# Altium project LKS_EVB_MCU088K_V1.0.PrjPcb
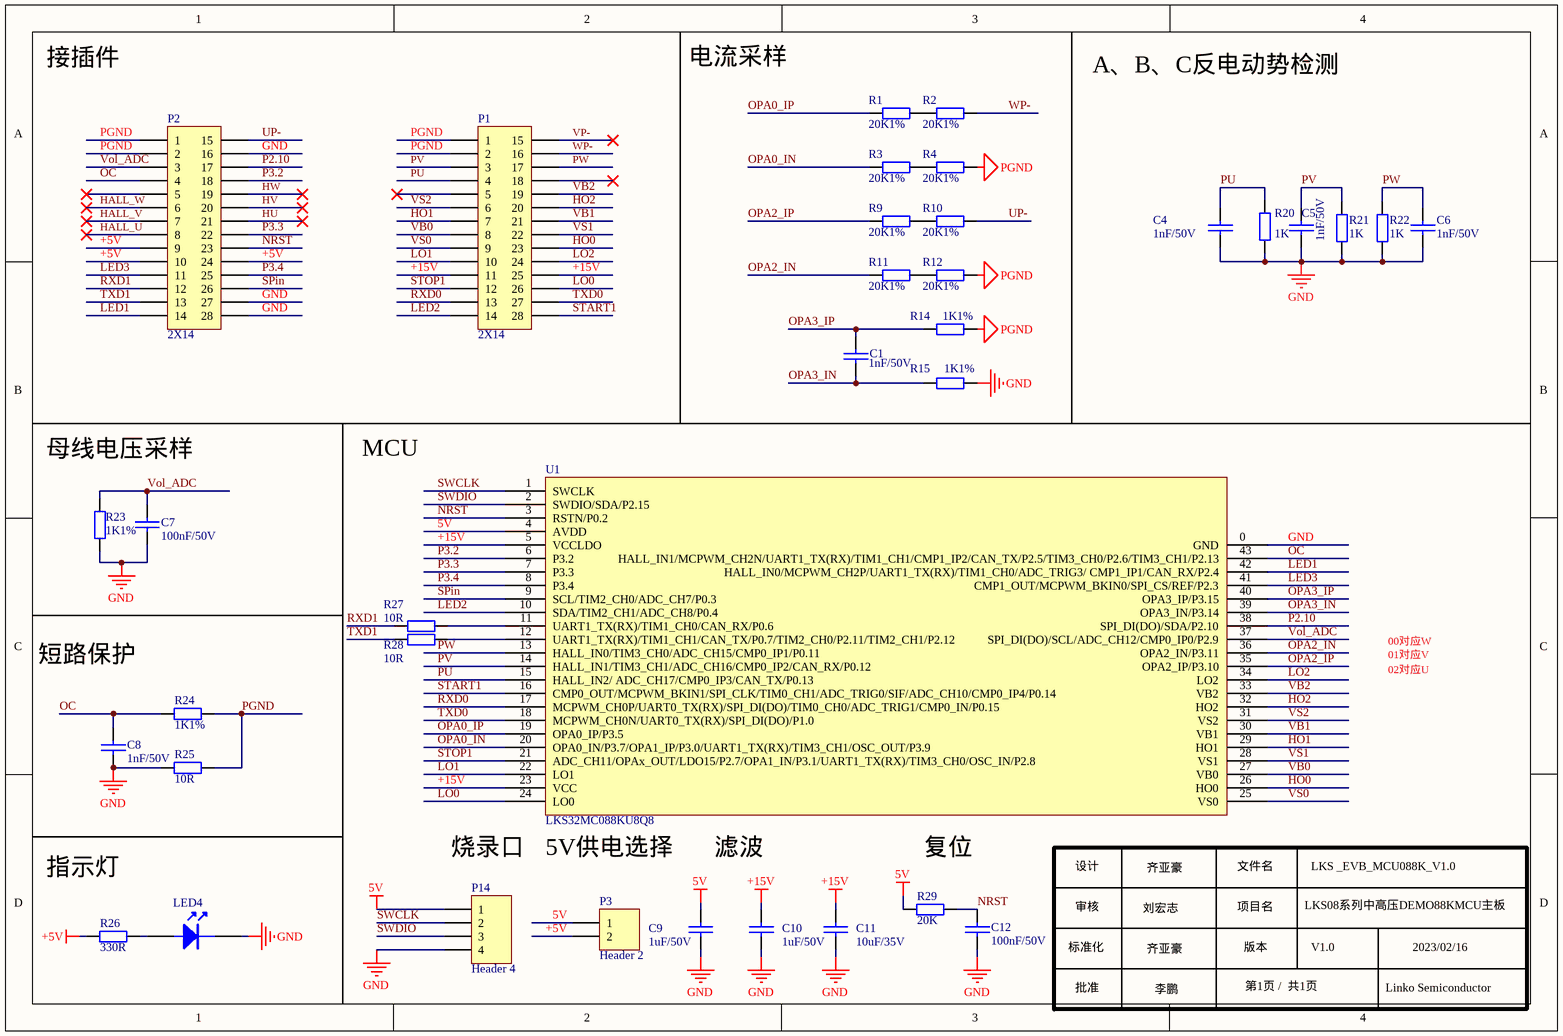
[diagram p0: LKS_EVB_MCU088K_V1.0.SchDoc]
1 sheet, 36 parts. Net scope: global (net labels, ports and power ports of the same name join across sheets).
Board file: LKS_EVB_MCU088K_V1.0.PcbDoc

## Sheet LKS_EVB_MCU088K_V1.0.SchDoc
size A4; SheetNumber: 1; SheetTotal: 1

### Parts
C1  1nF/50V  [0603C]
C4  1nF/50V  [0603C]
C5  1nF/50V  [0603C]
C6  1nF/50V  [0603C]
C7  100nF/50V  [0603C]
C8  1nF/50V  [0603C]
C9  1uF/50V  [0603C]
C10  1uF/50V  [0603C]
C11  10uF/35V  [0805C]
C12  100nF/50V  [0603C]
LED4  LED  [LED 0603R]  (value not drawn)
P1  2X14  [HDR 2X14 底层]
P2  2X14  [HDR 2X14 底层]
P3  Header 2  [HDR 1X2]
P14  Header 4  [HDR 1X4]
R1  20K1%  [0603R]
R2  20K1%  [0603R]
R3  20K1%  [0603R]
R4  20K1%  [0603R]
R9  20K1%  [0603R]
R10  20K1%  [0603R]
R11  20K1%  [0603R]
R12  20K1%  [0603R]
R14  1K1%  [0603R]
R15  1K1%  [0603R]
R20  1K  [0603R]
R21  1K  [0603R]
R22  1K  [0603R]
R23  1K1%  [0603R]
R24  1K1%  [0603R]
R25  10R  [0603R]
R26  330R  [0603R]
R27  10R  [0603R]
R28  10R  [0603R]
R29  20K  [0603R]
U1  LKS32MC088KU8Q8  [QFN43]

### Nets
5V: C9.2 P3.1 P14.1 R29.1 U1.4(AVDD)
+5V: P2.9 P2.10 P2.24 P3.2 R26.1
+15V: C10.2 C11.2 P1.11 P1.25 U1.5(VCCLDO) U1.23(VCC)
GND: C4.2 C5.2 C6.2 C7.1 C8.1 C9.1 C10.1 C11.1 C12.2 LED4.2(K) P2.16 P2.27 P2.28 P14.4 R15.1 R20.2 R21.2 R22.2 R23.1 R25.2 U1.0(GND)
PGND: P1.1 P1.2 P2.1 P2.2 R4.1 R12.1 R14.1 R24.2 R25.1
HALL_U: P2.8
HALL_V: P2.7
HALL_W: P2.6
HO0: P1.23 U1.26(HO0)
HO1: P1.7 U1.29(HO1)
HO2: P1.20 U1.32(HO2)
HU: P2.21
HV: P2.20
HW: P2.19
LED1: P2.14 U1.42(HALL_IN0/MCPWM_CH2P/UART1_TX(RX)/TIM1_CH0/ADC_TRIG3/_CMP1_IP1/CAN_RX/P2.4)
LED2: P1.14 U1.10(SDA/TIM2_CH1/ADC_CH8/P0.4)
LED3: P2.11 U1.41(CMP1_OUT/MCPWM_BKIN0/SPI_CS/REF/P2.3)
LO0: P1.26 U1.24(LO0)
LO1: P1.10 U1.22(LO1)
LO2: P1.24 U1.34(LO2)
NRST: C12.1 P2.23 R29.2 U1.3(RSTN/P0.2)
OC: C8.2 P2.4 R24.1 U1.43(HALL_IN1/MCPWM_CH2N/UART1_TX(RX)/TIM1_CH1/CMP1_IP2/CAN_TX/P2.5/TIM3_CH0/P2.6/TIM3_CH1/P2.13)
OPA0_IN: R3.2 U1.20(OPA0_IN/P3.7/OPA1_IP/P3.0/UART1_TX(RX)/TIM3_CH1/OSC_OUT/P3.9)
OPA0_IP: R1.2 U1.19(OPA0_IP/P3.5)
OPA2_IN: R11.2 U1.36(OPA2_IN/P3.11)
OPA2_IP: R9.2 U1.35(OPA2_IP/P3.10)
OPA3_IN: C1.2 R15.2 U1.39(OPA3_IN/P3.14)
OPA3_IP: C1.1 R14.2 U1.40(OPA3_IP/P3.15)
P2.10: P2.17 U1.38(SPI_DI(DO)/SDA/P2.10)
P3.2: P2.18 U1.6(P3.2)
P3.3: P2.22 U1.7(P3.3)
P3.4: P2.25 U1.8(P3.4)
PU: C4.1 P1.4 R20.1 U1.15(HALL_IN2/_ADC_CH17/CMP0_IP3/CAN_TX/P0.13)
PV: C5.1 P1.3 R21.1 U1.14(HALL_IN1/TIM3_CH1/ADC_CH16/CMP0_IP2/CAN_RX/P0.12)
PW: C6.1 P1.17 R22.1 U1.13(HALL_IN0/TIM3_CH0/ADC_CH15/CMP0_IP1/P0.11)
RXD0: P1.13 U1.17(MCPWM_CH0P/UART0_TX(RX)/SPI_DI(DO)/TIM0_CH0/ADC_TRIG1/CMP0_IN/P0.15)
RXD1: P2.12 R27.2
SPin: P2.26 U1.9(SCL/TIM2_CH0/ADC_CH7/P0.3)
START1: P1.28 U1.16(CMP0_OUT/MCPWM_BKIN1/SPI_CLK/TIM0_CH1/ADC_TRIG0/SIF/ADC_CH10/CMP0_IP4/P0.14)
STOP1: P1.12 U1.21(ADC_CH11/OPAx_OUT/LDO15/P2.7/OPA1_IN/P3.1/UART1_TX(RX)/TIM3_CH0/OSC_IN/P2.8)
SWCLK: P14.2 U1.1(SWCLK)
SWDIO: P14.3 U1.2(SWDIO/SDA/P2.15)
TXD0: P1.27 U1.18(MCPWM_CH0N/UART0_TX(RX)/SPI_DI(DO)/P1.0)
TXD1: P2.13 R28.1
UP-: P2.15 R10.1
VB0: P1.8 U1.27(VB0)
VB1: P1.21 U1.30(VB1)
VB2: P1.19 U1.33(VB2)
Vol_ADC: C7.2 P2.3 R23.2 U1.37(SPI_DI(DO)/SCL/ADC_CH12/CMP0_IP0/P2.9)
VP-: P1.15
VS0: P1.9 U1.25(VS0)
VS1: P1.22 U1.28(VS1)
VS2: P1.6 U1.31(VS2)
WP-: P1.16 R2.1
NetLED4_1: LED4.1(A) R26.2
NetR1_1: R1.1 R2.2
NetR3_1: R3.1 R4.2
NetR9_1: R9.1 R10.2
NetR11_1: R11.1 R12.2
NetR27_1: R27.1 U1.11(UART1_TX(RX)/TIM1_CH0/CAN_RX/P0.6)
NetR28_2: R28.2 U1.12(UART1_TX(RX)/TIM1_CH1/CAN_TX/P0.7/TIM2_CH0/P2.11/TIM2_CH1/P2.12)

Not connected (* = marked no-connect by the designer): P1 5* 18*; P2 5*

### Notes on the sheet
- 接插件
- 电流采样
- A、B、C反电动势检测
- 母线电压采样
- MCU
- 00对应W
- 短路保护
- 01对应V
- 02对应U
- 指示灯
- 烧录口
- (near U1) 5V供电选择
- (near U1) 滤波
- 复位
- 设计
- 审核
- 刘宏志
- 齐亚豪
- 文件名
- 项目名
- LKS08系列中高压DEMO88KMCU主板
- LKS _EVB_MCU088K_V1.0
- 标准化
- 批准
- 版本
- 第1页 /  共1页
- V1.0
- Linko Semiconductor
- 2023/02/16
- 李鹏

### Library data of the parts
C1 C7-C12 = C: Capacitor
C4-C6 = CAP: Capacitor
LED4 = LED: LED_Light
P1 P2 = 2X14: 双排针
P3 = Header 2: Header, 2-Pin
P14 = Header 4: Header, 4-Pin
R1-R4 R9-R12 R14 R15 R20-R24 R29 = Res: Resistor; Value: K
R25 = Res: Resistor; Value: 10
R26 = Res: Resistor; Value: 330
R27 = Res2: Resistor
R28 = Res2: Resistor; Value: 100R
U1 = LKS32MC088KU8Q8: 芯片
